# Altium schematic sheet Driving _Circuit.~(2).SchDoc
size A4; SheetNumber: 1; SheetTotal: 1
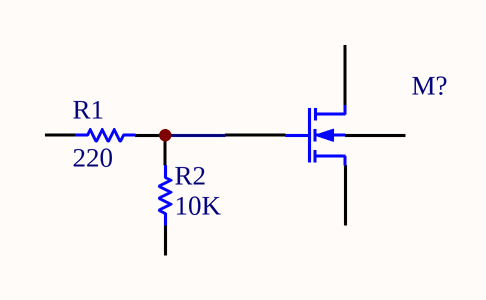
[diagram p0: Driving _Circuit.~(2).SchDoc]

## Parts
M?  N-channel MOS1 MOSFET Shichman and Hodges Model  (value not drawn)
R1  value 220  (hidden comment: Resistor)
R2  value 10K  (hidden comment: Resistor)

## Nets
NetM?_2: M?.2(G) R1.2 R2.2

Not connected (* = marked no-connect by the designer): M? 1(D) 3(S) 4(B); R1 1; R2 1

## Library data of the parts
M? = MOSFET N-ch Lev1: CBD: 0; FC: 0.5; IS: 1e-14; KP: 2e-05; PB: 0.8; PHI: 0.6; TNOM: 27; SimulationGenericComponent: True
R1 R2 = Resistor: TC1: 0; SimulationGenericComponent: True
